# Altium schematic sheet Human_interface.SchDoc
size A
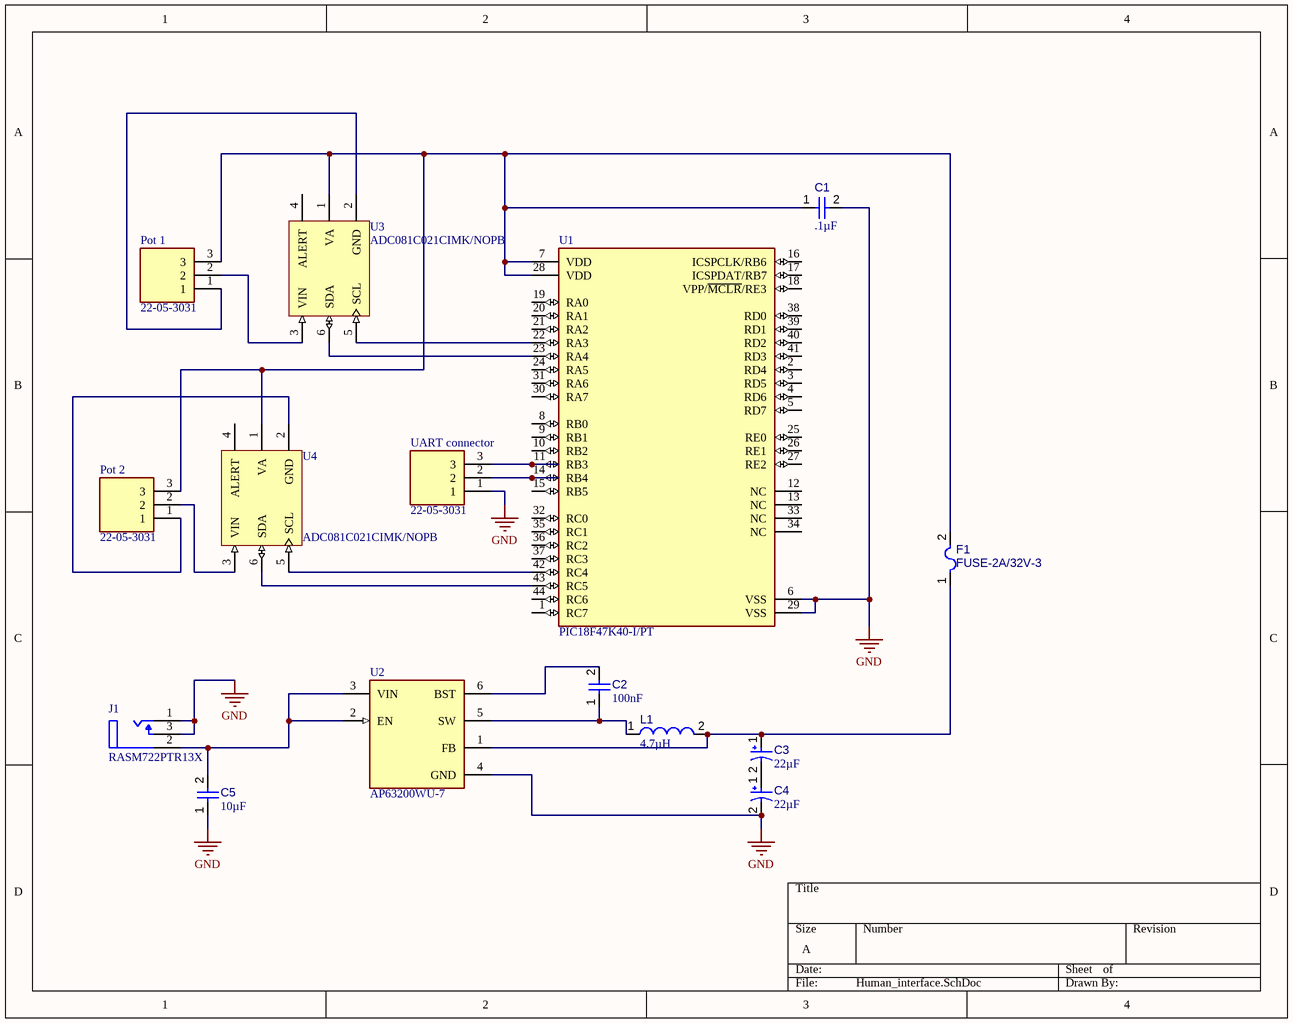
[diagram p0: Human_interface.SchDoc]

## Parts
C1  value .1µF  [CAPC1608X90X40LL10T20]  (hidden comment: Capacitor 1 uF +/- 10% 25 V 0603)
C2  value 100nF  [CAPC1608X90X40NL10T20]  (hidden comment: Capacitor 100 nF +/-10% 50 V 0603)
C3  value 22µF  [CAPPR55-250-1120X630X1220]  (hidden comment: ECA-2AM220)
C4  value 22µF  [CAPPR55-250-1120X630X1220]  (hidden comment: ECA-2AM220)
C5  value 10µF  [CAPC0603(1608)100_L]  (hidden comment: Capacitor 10µF +/-20% 10V 0603)
F1  FUSE-2A/32V-3  [LFUS-467_V]
J1  RASM722PTR13X  [FP-RASM722PTR13X-MFG]
L1  value 4.7µH  [INDR70-500-1220X900X1220]  (hidden comment: RLB9012-472KL)
Pot_1  22-05-3031  [SHDRRA3W87P0X254_1X3_747X818X660P]
Pot_2  22-05-3031  [SHDRRA3W87P0X254_1X3_747X818X660P]
U1  PIC18F47K40-I/PT  [FP-C04-076-IPC_A]
U2  AP63200WU-7  [FP-TSOT26-MFG]
U3  ADC081C021CIMK/NOPB  [MK06A_M]
U4  ADC081C021CIMK/NOPB  [MK06A_M]
UART_connector  22-05-3031  [SHDRRA3W87P0X254_1X3_747X818X660P]

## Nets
GND: C1.2 C4.2 C5.1 J1.1(TIP_TERMINAL(CENTER_PIN)) J1.3(SHUNT_TERMINAL) U1.6(VSS) U1.29(VSS) U2.4(GND) UART_connector.1
NetC1_1: C1.1 F1.2 Pot_1.3 Pot_2.3 U1.7(VDD) U1.28(VDD) U3.1(VA) U4.1(VA)
NetC2_1: C2.1 L1.1 U2.5(SW)
NetC2_2: C2.2 U2.6(BST)
NetC3_1: C3.1 F1.1 L1.2 U2.1(FB)
NetC3_2: C3.2 C4.1
NetC5_2: C5.2 J1.2(SLEEVE_TERMINAL) U2.2(EN) U2.3(VIN)
NetPot_1_1: Pot_1.1 U3.2(GND)
NetPot_1_2: Pot_1.2 U3.3(VIN)
NetPot_2_1: Pot_2.1 U4.2(GND)
NetPot_2_2: Pot_2.2 U4.3(VIN)
NetU1_11: U1.11(RB3) UART_connector.3
NetU1_14: U1.14(RB4) UART_connector.2
NetU1_22: U1.22(RA3) U3.5(SCL)
NetU1_23: U1.23(RA4) U3.6(SDA)
NetU1_42: U1.42(RC4) U4.5(SCL)
NetU1_43: U1.43(RC5) U4.6(SDA)

Not connected (* = marked no-connect by the designer): U1 1(RC7) 2(RD4) 3(RD5) 4(RD6) 5(RD7) 8(RB0) 9(RB1) 10(RB2) 12(NC) 13(NC) 15(RB5) 16(ICSPCLK/RB6) 17(ICSPDAT/RB7) 18(VPP/~{MCLR}/RE3) 19(RA0) 20(RA1) 21(RA2) 24(RA5) 25(RE0) 26(RE1) 27(RE2) 30(RA7) 31(RA6) 32(RC0) 33(NC) 34(NC) 35(RC1) 36(RC2) 37(RC3) 38(RD0) 39(RD1) 40(RD2) 41(RD3) 44(RC6); U3 4(ALERT); U4 4(ALERT)

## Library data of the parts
C1 = CMP-001-00005-6: Chip Capacitor, 1 uF, +/- 10%, 25 V, 0603 (1608 Metric); Capacitor Type: Ceramic; Voltage Rating: 25V
C2 = CMP-001-00017-6: Chip Capacitor, 100 nF, +/- 10%, 50 V, 0603 (1608 Metric); Voltage Rating: 50V; Capacitor Type: Ceramic
C3 C4 = CMP-001-00035-7: Aluminum Electrolytic Capacitor, 22 uF, +/- 20%, 100 V, -40 to 85 degC, 2-Pin THD, RoHS, Bulk; Manufacturer: Panasonic; Voltage Rating: 100V; Ripple Current: 115mA
C5 = CMP-001-00075-4: Chip Capacitor, 10µF +/-20%, 10V, 0603, Thickness 1 mm; Tolerance: 10%
F1 = CMP-005-00011-2: Fast Acting Fuse, 2 A, 32 V, -55 to 90 degC, 2-Pin SMD, RoHS, Tape and Reel; Current Rating: 2A
J1 = CMP-47995-000002-1: CONN PWR JACK 2.1X5.5MM SOLDER; Shielding: Unshielded; Gender: Male; Current Rating: 5A
L1 = CMP-006-00016-6: Radial Inductor, 4.7 mH, +/- 10%, 0.24 A, -55 to 125 degC, 2-Pin THD, RoHS, Bulk; Manufacturer: Bourns; Core Material: Ferrite; Shielding: Unshielded; Current Rating: 240mA; Q Factor: 15; Self Resonant Frequency: 500kHz; Inductance Tolerance: 5%
Pot_1 Pot_2 UART_connector = 22-05-3031: Connector; Manufacturer_Name: Molex
U1 = CMP-00000-1: RISC Microcontroller, 8-Bit, FLASH, 64MHz, CMOS, PQFP44
U2 = CMP-12757-000010-1: IC REG BUCK ADJUSTABLE 2A TSOT26; Manufacturer: Diodes Inc.; Switching Frequency: 500kHz; Max Supply Voltage: 32V; Number Of Outputs: 1; Nominal Supply Current: 22uA; Min Supply Voltage: 3.8V; Output Type: AdjustableProgrammable; Max Junction Temp: +160°C; Standoff Height: 0.01mm
U3 U4 = CMP-0054-00295-2: I2C-Compatible, 8-Bit Analog-to-Digital Converter with Alert Pin, 6-pin Tiny SOT23, Pb-Free; Manufacturer: National Semiconductor; PackageTopMarking: X34C*XTT; CompType: ADC IC; PowerWise: N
